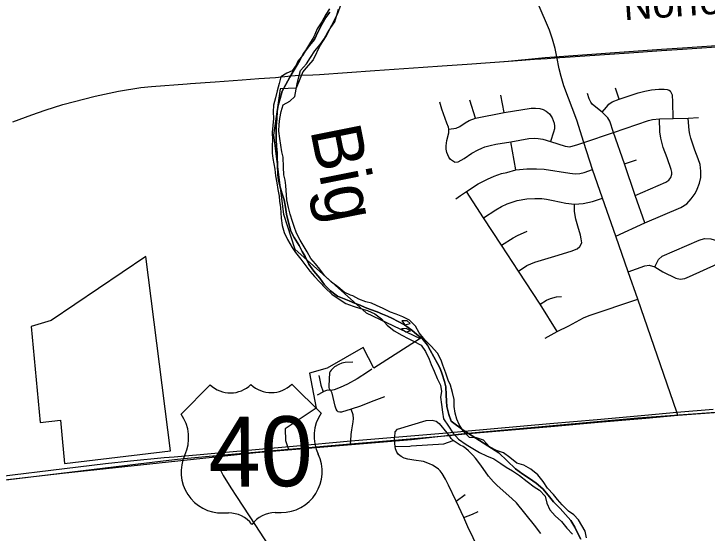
# Model space of a CAD drawing. Extents: x 114843 to 284848, y 317643 to 566895.
# Drawn here: x 135502 to 142391, y 380541 to 385704 of the extents above; entities that cross this region are included whole.
import ezdxf

# ---------------------------------------------------------------- set-up
doc = ezdxf.new("R2010")
doc.units = 0
for name, color, linetype in [('GM_X_Corporation', 7, 'Continuous'), ('GM_X_County', 7, 'Continuous'), ('GM_X_County_Road', 7, 'Continuous'), ('GM_X_Major_River', 7, 'Continuous'), ('GM_X_Major_River_Text', 7, 'Continuous'), ('GM_X_Rail_Line', 7, 'Continuous'), ('GM_X_Rail_Line_Text', 7, 'Continuous'), ('GM_X_Township', 7, 'Continuous'), ('GM_X_Township_Road', 7, 'Continuous'), ('GM_X_US_Location', 7, 'Continuous'), ('GM_X_US_Route', 7, 'Continuous'), ('GM_X_US_Shield', 7, 'Continuous')]:
    doc.layers.add(name, color=color, linetype=linetype)

msp = doc.modelspace()

# ---------------------------------------------------------------- linework, layer by layer
at = {"layer": 'GM_X_Corporation'}
msp.add_lwpolyline([(138777, 385874.6), (138715.8, 385698.5), (138604.7, 385484.5), (138545.1, 385393.5), (138477.8, 385248.2), (138404.9, 385164.1), (138374.2, 385128.7), (138336.5, 385038.3), (138306.7, 384966.4), (138147.4, 384957.2), (138081.2, 384496.8), (138181.1, 383710.9), (138293.6, 383363.8), (138570.8, 383116.7), (139001.7, 382732.6), (139538.7, 382474.4), (139079.4, 382181.1), (138973.4, 382386.7), (138615.5, 382180.2), (138440, 382131.3), (138507.5, 381781.8), (138196.4, 381577.7), (138202.3, 381462.7), (138232.1, 381372.3), (137486.8, 381306.1), (137580.4, 381113.4), (137659.4, 380991.8), (137715.6, 380905.2), (137902.1, 380618), (138787.5, 379254.4)], dxfattribs=at)
msp.add_lwpolyline([(135762.2, 381642.1), (135762.5, 381641), (135964.2, 381665.5), (135981, 381480.6), (136003.7, 381231.6), (137057.5, 381357.5), (136814.4, 383290.6), (135873, 382655.6), (135675.1, 382593.7)], close=True, dxfattribs=at)
at = {"layer": 'GM_X_County'}
for points in [[(138641.2, 385720.4), (138601.1, 385668.1), (138563, 385597.7), (138524.9, 385529.3), (138490.8, 385448.9), (138440.6, 385388.6), (138380.3, 385310.1), (138340.2, 385237.7), (138306.1, 385181.4), (138278, 385129.1), (138243.8, 385074.9), (138203.7, 385002.5), (138169.6, 384934.1), (138149.6, 384863.8), (138127.6, 384791.5), (138117.6, 384733.2), (138113.6, 384660.9), (138109.7, 384586.6), (138109.8, 384520.3), (138107.8, 384452), (138111.9, 384389.8), (138118, 384323.6), (138120.1, 384269.3), (138122.2, 384213.1), (138126.3, 384104.7), (138132.4, 384054.5), (138144.6, 383992.3), (138164.7, 383924.1), (138187, 383855.8), (138201.1, 383781.6), (138211.3, 383711.3), (138227.4, 383641.1), (138253.7, 383544.7), (138287.9, 383478.5), (138336.3, 383400.4), (138366.5, 383342.2), (138396.7, 383290), (138433, 383215.8), (138483.4, 383145.6), (138543.8, 383075.5), (138590.1, 383009.3), (138648.5, 382951.2), (138718.9, 382897.2), (138783.3, 382871.2), (138833.6, 382849.3), (138887.9, 382827.3), (138942.3, 382807.3), (138994.6, 382783.3), (139044.8, 382763.4), (139111.2, 382741.4), (139163.6, 382717.5), (139213.9, 382699.5), (139264.1, 382675.5), (139314.4, 382649.5), (139384.9, 382611.5), (139455.3, 382559.5), (139507.6, 382515.4), (139560, 382475.4), (139612.3, 382409.2), (139638.5, 382359.1), (139676.8, 382292.9), (139713.1, 382228.7), (139739.3, 382178.6), (139759.4, 382120.4), (139781.6, 382048.1), (139793.8, 381995.9), (139797.9, 381915.6), (139799.9, 381851.3), (139806, 381799.1), (139824.2, 381720.8), (139846.4, 381652.6), (139977.2, 381558.7), (140018.8, 381532.8), (140321.1, 381340.1), (140488.4, 381180.1), (140560.9, 381128), (140627.2, 381084), (140693.7, 381037.9), (140758.1, 380979.8), (140812.4, 380919.7), (140862.8, 380851.5), (140931.2, 380785.4), (140983.6, 380725.3), (141035.9, 380667.1), (141076.2, 380600.9), (141100.4, 380550.8), (141134.6, 380480.5)], [(141134.6, 380480.5), (141100.4, 380550.8), (141076.2, 380600.9), (141035.9, 380667.1), (140983.6, 380725.3), (140931.2, 380785.4), (140862.8, 380851.5), (140812.4, 380919.7), (140758.1, 380979.8), (140693.7, 381037.9), (140627.2, 381084), (140560.9, 381128), (140488.4, 381180.1), (140321.1, 381340.1), (140018.8, 381532.8), (139977.2, 381558.7), (139846.4, 381652.6), (139824.2, 381720.8), (139806, 381799.1), (139799.9, 381851.3), (139797.9, 381915.6), (139793.8, 381995.9), (139781.6, 382048.1), (139759.4, 382120.4), (139739.3, 382178.6), (139713.1, 382228.7), (139676.8, 382292.9), (139638.5, 382359.1), (139612.3, 382409.2), (139560, 382475.4), (139507.6, 382515.4), (139455.3, 382559.5), (139384.9, 382611.5), (139314.4, 382649.5), (139264.1, 382675.5), (139213.9, 382699.5), (139163.6, 382717.5), (139111.2, 382741.4), (139044.8, 382763.4), (138994.6, 382783.3), (138942.3, 382807.3), (138887.9, 382827.3), (138833.6, 382849.3), (138783.3, 382871.2), (138718.9, 382897.2), (138648.5, 382951.2), (138590.1, 383009.3), (138543.8, 383075.5), (138483.4, 383145.6), (138433, 383215.8), (138396.7, 383290), (138366.5, 383342.2), (138336.3, 383400.4), (138287.9, 383478.5), (138253.7, 383544.7), (138227.4, 383641.1), (138211.3, 383711.3), (138201.1, 383781.6), (138187, 383855.8), (138164.7, 383924.1), (138144.6, 383992.3), (138132.4, 384054.5), (138126.3, 384104.7), (138122.2, 384213.1), (138120.1, 384269.3), (138118, 384323.6), (138111.9, 384389.8), (138107.8, 384452), (138109.8, 384520.3), (138109.7, 384586.6), (138113.6, 384660.9), (138117.6, 384733.2), (138127.6, 384791.5), (138149.6, 384863.8), (138169.6, 384934.1), (138203.7, 385002.5), (138243.8, 385074.9), (138278, 385129.1), (138306.1, 385181.4), (138340.2, 385237.7), (138380.3, 385310.1), (138440.6, 385388.6), (138490.8, 385448.9), (138524.9, 385529.3), (138563, 385597.7), (138601.1, 385668.1), (138641.2, 385720.4)]]:
    msp.add_lwpolyline(points, dxfattribs=at)
at = {"layer": 'GM_X_County_Road'}
msp.add_lwpolyline([(142099.1, 381713), (142088.9, 381742.4), (141700.9, 382868.6), (141606.5, 383138.5), (141484.1, 383494.9), (141351.5, 383870.1), (141253.6, 384157.7), (141166.9, 384425.1), (141095.4, 384647.6), (140966.2, 384988.9), (140939.1, 385079.5), (140919.6, 385156.9), (140898, 385275.8), (140882.3, 385360.8), (140853.3, 385451.5), (140825.4, 385542.2), (140600.2, 386069.1), (140391.4, 386603.1)], dxfattribs=at)
at = {"layer": 'GM_X_Major_River'}
for points in [[(138871.2, 382900), (138847.3, 382908), (138783.3, 382938.2), (138721.4, 382990.3), (138657.5, 383034.5), (138591.7, 383100.6), (138541.8, 383166.8), (138499.9, 383216.9), (138454, 383273), (138418.2, 383337.2), (138388.3, 383387.3), (138348.4, 383453.4), (138310.6, 383521.6), (138286.7, 383589.7), (138270.8, 383639.8), (138247, 383711.9), (138231.1, 383778), (138215.3, 383856.1), (138203.5, 383996.3), (138197.7, 384050.4), (138185.8, 384102.5), (138181.9, 384178.6), (138178.1, 384278.7), (138166.2, 384330.8), (138154.4, 384398.9), (138144.5, 384465), (138134.6, 384537.1), (138138.8, 384603.2), (138144.9, 384663.2), (138157, 384733.3), (138179.2, 384799.4), (138243.2, 384835.3), (138295.3, 384883.3), (138307.5, 384955.4), (138317.6, 385009.4), (138333.7, 385077.5), (138351.8, 385141.5), (138409.9, 385207.5), (138450.1, 385269.6), (138492.2, 385335.6), (138546.3, 385399.6), (138584.4, 385455.6), (138618.5, 385515.6), (138650.6, 385567.7), (138690.8, 385623.7), (138712.9, 385691.7), (138729, 385751.8)], [(138637, 385753.9), (138602.9, 385695.9), (138562.8, 385623.8), (138514.6, 385553.8), (138482.5, 385475.8), (138448.4, 385423.7), (138410.2, 385355.7), (138372.1, 385293.7), (138324, 385231.7), (138307.9, 385193.6)], [(138307.9, 385193.6), (138267.8, 385137.6), (138213.8, 385113.7), (138155.7, 385077.7), (138139.6, 385011.7), (138119.4, 384937.6), (138101.3, 384869.5), (138083.2, 384797.5), (138079, 384729.4), (138080.9, 384663.3), (138076.8, 384595.2), (138068.6, 384525.2), (138070.5, 384453.1), (138068.3, 384387), (138068.2, 384318.9), (138076.1, 384264.8), (138084, 384212.7), (138093.9, 384160.7), (138101.7, 384094.6), (138115.6, 384024.5), (138125.5, 383958.4), (138139.3, 383892.3), (138143.2, 383842.2), (138151.1, 383778.1), (138155, 383724), (138156.9, 383674), (138166.7, 383599.8), (138188.6, 383529.7), (138220.4, 383461.6), (138266.3, 383381.4), (138300.2, 383331.3), (138354, 383263.2), (138393.9, 383213), (138443.8, 383144.9), (138489.7, 383090.8), (138539.6, 383040.6), (138599.4, 382976.5), (138661.3, 382918.3), (138733.2, 382868.1), (138801.1, 382824), (138875, 382797.9), (138947, 382773.7), (139016.9, 382755.6), (139088.9, 382721.5), (139154.8, 382671.3), (139212.6, 382607.1), (139282.5, 382551), (139356.4, 382508.8), (139420.3, 382474.7)], [(139839.3, 382011.5), (139817.4, 382061.6), (139793.6, 382129.7), (139763.7, 382211.9), (139747.8, 382262), (139712, 382330.1), (139650.1, 382398.3), (139584.3, 382462.5), (139528.4, 382532.6), (139494.6, 382598.8), (139434.7, 382656.9), (139366.8, 382691.1), (139300.8, 382717.2), (139244.9, 382737.3), (139173, 382773.4), (139107, 382803.6), (139055.1, 382825.7), (139001.1, 382839.7), (138931.2, 382867.9), (138871.2, 382900)], [(139358.7, 382651), (139388.6, 382612.9), (139440.6, 382624.9)], [(139440.6, 382624.9), (139408.7, 382650.9), (139358.7, 382651)], [(139444.5, 382550.8), (139400.5, 382576.9), (139354.5, 382572.9)], [(139354.5, 382572.9), (139396.5, 382540.8), (139444.5, 382550.8)], [(139420.3, 382474.7), (139474.3, 382448.6), (139550.2, 382408.4), (139594, 382346.3), (139627.9, 382270.1), (139647.8, 382218), (139677.6, 382149.9), (139707.5, 382077.7), (139741.3, 382013.6), (139751.2, 381947.5), (139743.1, 381893.4), (139750.9, 381819.3), (139760.8, 381743.2), (139772.6, 381677.1), (139822.5, 381604.9), (139864.3, 381536.7), (139920.2, 381476.6), (139998.1, 381422.4), (140062, 381382.2), (140127.9, 381344.1), (140197.8, 381307.9), (140271.7, 381279.8), (140341.6, 381231.6), (140393.5, 381197.5), (140455.5, 381159.4), (140525.4, 381113.2), (140601.2, 381053), (140673.1, 381002.8), (140725, 380968.7), (140782.9, 380908.5), (140796.7, 380840.4), (140828.6, 380772.3), (140882.5, 380712.1), (140942.3, 380655.9), (140998.2, 380589.8), (141054.1, 380531.6)], [(141192, 380493.3), (141180.1, 380561.5), (141146.2, 380617.6), (141112.4, 380671.7), (141066.5, 380723.9), (141014.6, 380758), (140950.7, 380822.2), (140902.8, 380876.3), (140862.9, 380926.5), (140805.1, 380988.6), (140761.2, 381052.8), (140709.4, 381119), (140639.5, 381175.2), (140569.6, 381215.3), (140499.6, 381235.4), (140429.7, 381291.6), (140367.9, 381339.8), (140297.9, 381361.9), (140228, 381398), (140168.1, 381464.2), (140098.2, 381488.3), (140030.2, 381490.4), (139970.3, 381550.6), (139928.5, 381620.8), (139902.6, 381674.9), (139888.7, 381735), (139876.9, 381801.1), (139877, 381869.2), (139859.2, 381939.3), (139839.3, 382011.5)]]:
    msp.add_lwpolyline(points, dxfattribs=at)
at = {"layer": 'GM_X_Rail_Line'}
for points in [[(138255.7, 385088.7), (138341.1, 385093), (138474.2, 385097.8), (138540.1, 385102.3), (139089, 385140.7), (139570.8, 385174.5), (139757.1, 385186.4), (140006.9, 385203.8), (140464.9, 385238), (140676.6, 385252.1), (140800.5, 385260.3), (140876.6, 385265.3), (141029.9, 385275.9), (141615.7, 385315.8), (141937.6, 385339.5), (142146.2, 385353.5), (143395, 385439.7), (144024.7, 385484.7), (144633.1, 385525.3), (145432.1, 385582.2), (146098.7, 385629.1)], [(140380, 385231.6), (140780.7, 385270.3), (141936.7, 385352.6), (142145.3, 385366.6), (143394.1, 385452.8), (144023.8, 385497.8), (144632.2, 385538.4), (145431.2, 385595.3), (146097.8, 385642.2)], [(135492.3, 384630.5), (135681.9, 384700.9), (135814.2, 384745.8), (135989.9, 384801.7), (136309.9, 384886.2), (136543.4, 384934.3), (136762.1, 384972.4), (136869.7, 384983), (137222.9, 385008.2), (137256.4, 385011.3), (137503.3, 385028.1), (137770.1, 385047.9), (137936.8, 385060.1), (138103.1, 385071.8), (138255.7, 385088.7)], [(139976.5, 381530.3), (141701.6, 381686.5), (142931.4, 381776.7), (145058.8, 381883.3), (151605.9, 382247), (160057.2, 382729.4), (166949.7, 383110), (174406.2, 383574.4), (180366.1, 383984.7)], [(129506.6, 380556.5), (133082.1, 380801.3), (135985.5, 381135.4), (137907.6, 381341.1), (139453.6, 381470.5), (139976.5, 381530.3)]]:
    msp.add_lwpolyline(points, dxfattribs=at)
at = {"layer": 'GM_X_Township'}
for points in [[(138641.2, 385720.4), (138601.1, 385668.1), (138563, 385597.7), (138524.9, 385529.3), (138490.8, 385448.9), (138440.6, 385388.6), (138380.3, 385310.1), (138340.2, 385237.7), (138306.1, 385181.4), (138278, 385129.1), (138243.8, 385074.9), (138203.7, 385002.5), (138169.6, 384934.1), (138149.6, 384863.8), (138127.6, 384791.5), (138117.6, 384733.2), (138113.6, 384660.9), (138109.7, 384586.6), (138109.8, 384520.3), (138107.8, 384452), (138111.9, 384389.8), (138118, 384323.6), (138120.1, 384269.3), (138122.2, 384213.1), (138126.3, 384104.7), (138132.4, 384054.5), (138144.6, 383992.3), (138164.7, 383924.1), (138187, 383855.8), (138201.1, 383781.6), (138211.3, 383711.3), (138227.4, 383641.1), (138253.7, 383544.7), (138287.9, 383478.5), (138336.3, 383400.4), (138366.5, 383342.2), (138396.7, 383290), (138433, 383215.8), (138483.4, 383145.6), (138543.8, 383075.5), (138590.1, 383009.3), (138648.5, 382951.2), (138718.9, 382897.2), (138783.3, 382871.2), (138833.6, 382849.3), (138887.9, 382827.3), (138942.3, 382807.3), (138994.6, 382783.3), (139044.8, 382763.4), (139111.2, 382741.4), (139163.6, 382717.5), (139213.9, 382699.5), (139264.1, 382675.5), (139314.4, 382649.5), (139384.9, 382611.5), (139455.3, 382559.5), (139507.6, 382515.4), (139560, 382475.4), (139612.3, 382409.2), (139638.5, 382359.1), (139676.8, 382292.9), (139713.1, 382228.7), (139739.3, 382178.6), (139759.4, 382120.4), (139781.6, 382048.1), (139793.8, 381995.9), (139797.9, 381915.6), (139799.9, 381851.3), (139806, 381799.1), (139824.2, 381720.8), (139846.4, 381652.6), (139977.2, 381558.7), (140018.8, 381532.8), (140321.1, 381340.1), (140488.4, 381180.1), (140560.9, 381128), (140627.2, 381084), (140693.7, 381037.9), (140758.1, 380979.8), (140812.4, 380919.7), (140862.8, 380851.5), (140931.2, 380785.4), (140983.6, 380725.3), (141035.9, 380667.1), (141076.2, 380600.9), (141100.4, 380550.8), (141134.6, 380480.5)], [(141134.6, 380480.5), (141100.4, 380550.8), (141076.2, 380600.9), (141035.9, 380667.1), (140983.6, 380725.3), (140931.2, 380785.4), (140862.8, 380851.5), (140812.4, 380919.7), (140758.1, 380979.8), (140693.7, 381037.9), (140627.2, 381084), (140560.9, 381128), (140488.4, 381180.1), (140321.1, 381340.1), (140018.8, 381532.8), (139977.2, 381558.7), (139846.4, 381652.6), (139824.2, 381720.8), (139806, 381799.1), (139799.9, 381851.3), (139797.9, 381915.6), (139793.8, 381995.9), (139781.6, 382048.1), (139759.4, 382120.4), (139739.3, 382178.6), (139713.1, 382228.7), (139676.8, 382292.9), (139638.5, 382359.1), (139612.3, 382409.2), (139560, 382475.4), (139507.6, 382515.4), (139455.3, 382559.5), (139384.9, 382611.5), (139314.4, 382649.5), (139264.1, 382675.5), (139213.9, 382699.5), (139163.6, 382717.5), (139111.2, 382741.4), (139044.8, 382763.4), (138994.6, 382783.3), (138942.3, 382807.3), (138887.9, 382827.3), (138833.6, 382849.3), (138783.3, 382871.2), (138718.9, 382897.2), (138648.5, 382951.2), (138590.1, 383009.3), (138543.8, 383075.5), (138483.4, 383145.6), (138433, 383215.8), (138396.7, 383290), (138366.5, 383342.2), (138336.3, 383400.4), (138287.9, 383478.5), (138253.7, 383544.7), (138227.4, 383641.1), (138211.3, 383711.3), (138201.1, 383781.6), (138187, 383855.8), (138164.7, 383924.1), (138144.6, 383992.3), (138132.4, 384054.5), (138126.3, 384104.7), (138122.2, 384213.1), (138120.1, 384269.3), (138118, 384323.6), (138111.9, 384389.8), (138107.8, 384452), (138109.8, 384520.3), (138109.7, 384586.6), (138113.6, 384660.9), (138117.6, 384733.2), (138127.6, 384791.5), (138149.6, 384863.8), (138169.6, 384934.1), (138203.7, 385002.5), (138243.8, 385074.9), (138278, 385129.1), (138306.1, 385181.4), (138340.2, 385237.7), (138380.3, 385310.1), (138440.6, 385388.6), (138490.8, 385448.9), (138524.9, 385529.3), (138563, 385597.7), (138601.1, 385668.1), (138641.2, 385720.4)]]:
    msp.add_lwpolyline(points, dxfattribs=at)
at = {"layer": 'GM_X_Township_Road'}
for p, q in [((141515.7, 384855.2), (141479.8, 384963.6)), ((140089.6, 384667.9), (140031.8, 384844.3)), ((140373.1, 384721.7), (140341.8, 384894.7)), ((140488.5, 384152.3), (140440.2, 384432.3)), ((141569.4, 384211.9), (141689, 384253.5)), ((138518.3, 381917.1), (138574.6, 381946.2)), ((138847.4, 381429.2), (138849.1, 381457.7)), ((139292.3, 381403.7), (139284.8, 381465)), ((139895.9, 380858.9), (139987.3, 380923.6)), ((139972.2, 380696.2), (139895.9, 380858.9))]:
    msp.add_line(p, q, dxfattribs=at)
for points in [[(141461.4, 384523.4), (141423, 384637.2), (141403.6, 384670.2), (141379.9, 384693), (141346.5, 384727.8), (141252.2, 384802.4), (141234.8, 384824.7), (141218, 384858.2), (141201.1, 384911.6)], [(141346.5, 384727.8), (141391, 384777), (141414.7, 384806.7), (141446.5, 384828.6), (141515.7, 384855.2), (141707.1, 384917.2), (141771.4, 384934.8), (141836.9, 384947.4), (141912.1, 384954.4), (141963.7, 384956), (141995.6, 384952.4), (142014.1, 384944.9), (142026.4, 384933.5)], [(142055, 384664.1), (142049.4, 384829.1), (142045.7, 384894.1), (142037.9, 384916.4), (142026.4, 384933.5)], [(139879.8, 384230.3), (139840.6, 384256.5), (139824.2, 384280.5), (139805.2, 384326), (139798.3, 384357.9), (139796.3, 384390.3), (139806.1, 384444.5), (139823.6, 384519.2), (139822.8, 384555.9), (139820.8, 384577), (139806.1, 384615.3), (139755.8, 384757), (139734.8, 384826.6)], [(139822.8, 384555.9), (139897.8, 384567.9), (139933.8, 384582.6), (139986.5, 384620.2), (140024.8, 384642.2), (140089.6, 384667.9), (140373.1, 384721.7), (140643.5, 384764.5), (140686.8, 384767.3), (140728.9, 384762.7), (140760.3, 384753.3), (140792.9, 384735.5), (140823.1, 384709.3), (140852.3, 384669.8), (140870.7, 384615.8), (140875.7, 384585.8), (140873.5, 384559.3), (140865.3, 384526.7), (140835.9, 384435.1)], [(140835.9, 384435.1), (140980.6, 384386.8), (141026.4, 384381.3), (141105.3, 384404.9), (141166.9, 384425.1), (141461.4, 384523.4), (141807.3, 384641.9), (141848, 384652.4), (141916.8, 384659.3), (142055, 384664.1), (142203.5, 384667.7), (142305.5, 384672.3)], [(142030.6, 384076.3), (142041.8, 384108.2), (142040.4, 384128.6), (142032.6, 384155.3), (141994.8, 384271), (141955.8, 384376.6), (141929.6, 384466.9), (141921.5, 384530.6), (141916.8, 384659.3)], [(142292.6, 383960.8), (142315.3, 384020.9), (142328.9, 384075.9), (142329.7, 384139.6), (142320.3, 384207.1), (142302, 384263), (142270.5, 384348.3), (142229.2, 384469), (142218.7, 384507.2), (142212.1, 384545.4), (142203.5, 384667.7)], [(141772.5, 383624.4), (141677.5, 383896.5), (141569.4, 384211.9), (141461.4, 384523.4)], [(139879.8, 384230.3), (139916.5, 384231.2), (139975.8, 384265.3), (140054.3, 384317), (140114.7, 384351.1), (140151.9, 384367.6), (140183.7, 384381.1), (140235.9, 384396.5), (140291.2, 384408.3), (140440.2, 384432.3), (140619.2, 384466), (140670.9, 384468.8), (140711.8, 384464.3), (140757.6, 384456.2), (140835.9, 384435.1)], [(139893.9, 383864.1), (139939.4, 383897.5), (140000.5, 383937.1), (140115.4, 384012.5), (140207.6, 384061.3), (140273.6, 384090.6), (140349.2, 384116.4), (140399.6, 384127.6), (140488.5, 384152.3), (140599.1, 384162.7), (140693.9, 384163.3), (140772.3, 384159.2), (141028.4, 384119.8), (141078.4, 384114.5), (141125.9, 384115.7), (141167.7, 384124.8), (141253.6, 384157.7)], [(141677.5, 383896.5), (141981.2, 384030), (142010.4, 384049.3), (142030.6, 384076.3)], [(140901.9, 382546.4), (140730.9, 382816.5), (140517.6, 383146.5), (140346.7, 383404.7), (140170.4, 383677.3), (140000.5, 383937.1)], [(141484.1, 383494.9), (141772.5, 383624.4), (142128.3, 383778.7), (142188, 383816.1), (142233.5, 383863.6), (142272.7, 383918.6), (142292.6, 383960.8)], [(140170.4, 383677.3), (140291.7, 383756.1), (140347.8, 383788), (140405.3, 383814.6), (140504, 383846.8), (140598.1, 383863.1), (140677.5, 383869.2), (140748.4, 383867.3), (140795.9, 383862), (140861.2, 383848.8), (140985.5, 383821.5), (141073.3, 383810.9), (141157.8, 383817.1), (141253.5, 383837.1), (141351.5, 383870.1)], [(140517.6, 383146.5), (140598.4, 383203.4), (140678.1, 383235.4), (140878.1, 383294.5), (141038.9, 383345.4), (141100.4, 383368.1), (141125.1, 383390.6), (141144.5, 383426.1), (141140.3, 383468), (141131.2, 383503.6), (141105, 383593.8), (141086.9, 383661.9), (141074.7, 383740), (141073.3, 383810.9)], [(140346.7, 383404.7), (140462.8, 383476.3), (140505.8, 383500.2), (140603.8, 383542.8)], [(141871.7, 383189.3), (141906.9, 383261), (141943.6, 383293.2), (142310.5, 383452.2), (142364.5, 383468.6), (142427.3, 383466.6), (142484, 383449.8), (142550.7, 383413.3), (142594.2, 383363.2), (142634.2, 383282.2)], [(141606.5, 383138.5), (141770.7, 383199.7), (141815, 383203.7), (141871.7, 383189.3), (141950.8, 383139.4), (142081.7, 383075.1), (142122.4, 383066.8), (142170.4, 383073.3), (142214.6, 383090.9), (142634.2, 383282.2), (142759.3, 383336)], [(140730.9, 382816.5), (140796.1, 382858.2), (140833.4, 382874.2), (140894.8, 382889), (140943.3, 382894.6)], [(140782.4, 382480.7), (140901.9, 382546.4), (141015.5, 382602.9), (141163, 382680.6), (141219.2, 382704.6), (141700.9, 382868.6)], [(138871.7, 382239.2), (138793.5, 382236.9), (138762.7, 382229.3), (138732.1, 382217.4), (138689.6, 382193.2), (138655, 382162.2), (138644.3, 382148.4), (138639.3, 382133.5), (138631.7, 382004.7), (138632.3, 381987.8), (138635.8, 381975.8), (138652.2, 381959.8)], [(139057.6, 382172.5), (139017, 382141.7), (138912.1, 382075.6), (138817, 382021.2), (138745.1, 381987.7), (138685.7, 381966.4), (138652.2, 381959.8)], [(138533.6, 382109.4), (138538.4, 382077), (138551.6, 382012.7), (138574.6, 381946.2)], [(138652.2, 381959.8), (138618.8, 381961.4), (138599.5, 381957), (138574.6, 381946.2)], [(138854.8, 381772.7), (138758.1, 381743.8), (138741.8, 381743.4), (138726.2, 381748.3), (138713.6, 381758.4), (138705.3, 381772.6), (138695.3, 381803.9), (138664.9, 381931.7), (138652.2, 381959.8)], [(139185.5, 381897.3), (139054.2, 381844.9), (138945.6, 381803.6), (138854.8, 381772.7)], [(138849.1, 381457.7), (138853, 381520.3), (138860.2, 381568.9), (138874.8, 381647.8), (138877.6, 381679.7), (138872.8, 381716), (138854.8, 381772.7)], [(139286.2, 381494.4), (139289.8, 381546.4), (139313.6, 381573), (139597.6, 381660.7), (139657.4, 381665), (139697.8, 381653.1), (139729.4, 381630.9), (139804.2, 381539.7), (139825.7, 381512.6), (139837.5, 381498.4)], [(139284.8, 381465), (139285.5, 381483.2), (139286.2, 381494.4)], [(139292.3, 381403.7), (139435.5, 381407), (139451.5, 381409.8), (139613.7, 381417.2), (139775.7, 381427.8), (139866.8, 381460.4)], [(139866.8, 381460.4), (139849, 381482.9), (139837.5, 381498.4)], [(140738.7, 380538), (140676.4, 380619.1), (140498.4, 380840.8), (140451.1, 380884.8), (140304.4, 381013.1), (140266.7, 381049.8), (140217, 381108.8), (140143.5, 381215.7), (140089, 381286.3), (140062.9, 381317.2), (140021.4, 381359.2), (139992.5, 381383.8), (139965.5, 381402.3), (139936.1, 381416.6), (139866.8, 381460.4)], [(139895.9, 380858.9), (139821.5, 381017.9), (139791.7, 381076.1), (139758.6, 381132.1), (139739.5, 381158.6), (139722.7, 381175.3), (139689.6, 381200), (139661.7, 381216.7), (139632.7, 381230.9), (139571.8, 381254.4), (139475.2, 381266.6), (139418.5, 381276.6), (139380, 381287.3), (139350.8, 381301.1), (139325.3, 381321.2), (139308.2, 381344.4), (139295.7, 381378.1), (139292.3, 381403.7)], [(139972.2, 380696.2), (140058.9, 380729.2), (140115.7, 380754.9)], [(140118.9, 380385.1), (140014.4, 380603.8), (139972.2, 380696.2)]]:
    msp.add_lwpolyline(points, dxfattribs=at)
at = {"layer": 'GM_X_US_Route'}
for p, q in [((138276.6, 381405.7), (138849.1, 381457.7)), ((138274, 381379.1), (138847.4, 381429.2))]:
    msp.add_line(p, q, dxfattribs=at)
for points in [[(139978.4, 381555.8), (140828.7, 381630.1), (141299.4, 381671.5), (141773.1, 381714.1), (142088.9, 381742.4), (142452.6, 381771.9)], [(140020, 381530), (140839.2, 381601.4), (141309.5, 381642.9), (141783.2, 381684.6), (142099.1, 381713), (142460.3, 381741.8)], [(138847.4, 381429.2), (139284.8, 381465), (139825.7, 381512.6), (140020, 381530)], [(138849.1, 381457.7), (139286.2, 381494.4), (139804.2, 381539.7), (139978.4, 381555.8)], [(137095.9, 381300.6), (137940.4, 381375.2), (138276.6, 381405.7)], [(137096.8, 381272.1), (137191, 381282.8), (137516.4, 381312.9), (138274, 381379.1)], [(134942.3, 381053.7), (136413.7, 381231.9), (136660.6, 381259.8), (136995.7, 381291.7), (137095.9, 381300.6)], [(134944, 381014.2), (135534, 381084.4), (136735.7, 381230.7), (137096.8, 381272.1)]]:
    msp.add_lwpolyline(points, dxfattribs=at)
at = {"layer": 'GM_X_US_Shield'}
for p, q in [((137451.9, 382016.6), (137164, 381724.5)), ((138556.2, 381734.5), (138264.1, 382022.5)), ((137577.1, 380741.3), (137635.1, 380741.7)), ((138099.2, 380745), (138157.2, 380745.4))]:
    msp.add_line(p, q, dxfattribs=at)
for centre, radius, start, end in [((137653.5, 382225.2), 290.1, 225.98472, 314.83873), ((138059.6, 382228.2), 290.1, 225.98473, 314.83874), ((138890.5, 381504), 406.1, 145.41082, 205.86462), ((136833, 381489.2), 406.1, 334.95884, 35.41265), ((137569.7, 381147.3), 406.1, 155.24364, 271.04998), ((138158.8, 381151.5), 406.1, 269.77349, 25.57983), ((137637.2, 380451.6), 290.1, 37.28163, 90.41173), ((138101.3, 380455), 290.1, 90.41174, 143.54184)]:
    msp.add_arc(centre, radius, start, end, dxfattribs=at)

# ---------------------------------------------------------------- texts
at = {"layer": 'GM_X_Major_River_Text'}
msp.add_text('Big', height=500.06, rotation=281.28549, dxfattribs=at).set_placement((138445.6, 384549.2))
at = {"layer": 'GM_X_Rail_Line_Text'}
msp.add_text('Norfolk', height=299.02, rotation=3.98825, dxfattribs=at).set_placement((141565.9, 385639.4))
at = {"layer": 'GM_X_US_Location'}
for s, rotation, p in [('0', 0.41173, (137862.5, 381347)), ('/', 0.41173, (137862.6, 381347)), ('40', 0.41174, (137657.5, 381138.5))]:
    msp.add_text(s, height=1, rotation=rotation, dxfattribs=at).set_placement(p)
at = {"layer": 'GM_X_US_Shield'}
msp.add_text('40', height=696.14, rotation=0.41173, dxfattribs=at).set_placement((137438.1, 381001.3))

doc.saveas('drawing.dxf')
